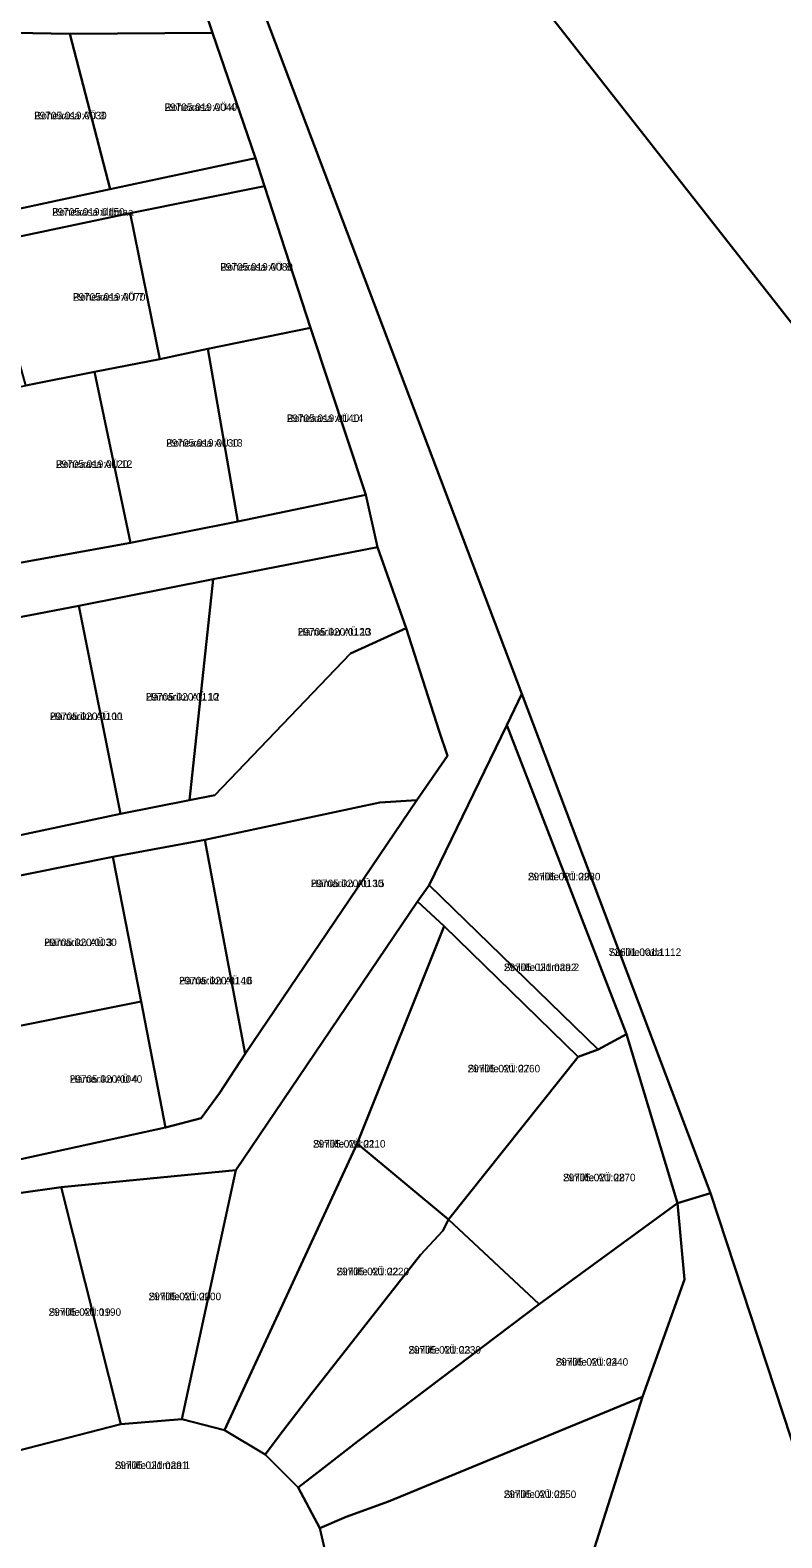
# Model space of a CAD drawing. Extents: x 504287 to 537970, y 6539941 to 6586214.
# Drawn here: x 519555.2 to 519705.5, y 6562734.5 to 6563035.9 of the extents above; entities that cross this region are included whole.
import ezdxf

# ---------------------------------------------------------------- set-up
doc = ezdxf.new("R2010")
doc.units = 0
for name, color, linetype in [('L_AADRESS', 7, 'Continuous'), ('PIIR', 7, 'Continuous'), ('TUNNUS', 7, 'Continuous')]:
    doc.layers.add(name, color=color, linetype=linetype)

msp = doc.modelspace()

# ---------------------------------------------------------------- linework, layer by layer
at = {"layer": 'PIIR'}
for points in [[(519599.74, 6563045.34), (519621.02, 6563054.62), (519628.3, 6563057.8), (519628.55, 6563077.91), (519761.64, 6562908.34), (519935.24, 6562630.59), (519776.33, 6562544.79), (519691.31, 6562803.36), (519653.53, 6562903.18)], [(519379.09, 6562978.83), (519372.84, 6562987.83), (519384.54, 6562993.66), (519400.83, 6563002.24), (519416.85, 6563010.23), (519433.17, 6563018.85), (519452.23, 6563026.37), (519470.82, 6563031.67), (519483.82, 6563036.19), (519500.29, 6563041.06), (519518.28, 6563044.73), (519537.55, 6563044.73), (519555.2, 6563044.87), (519572.77, 6563044.98), (519588.48, 6563045.08), (519591.71, 6563035.32), (519563.15, 6563035.15), (519540.86, 6563035.52), (519516.8, 6563034.6), (519500.02, 6563030.32), (519441.15, 6563010.5), (519419.88, 6562999.55), (519403.66, 6562991.39), (519386.67, 6562982.83)], [(519540.86, 6563035.52), (519563.15, 6563035.15), (519571.21, 6563004.1), (519548.61, 6562999.2)], [(519563.15, 6563035.15), (519591.71, 6563035.32), (519600.31, 6563010.25), (519571.21, 6563004.1)], [(519525.83, 6562994.92), (519548.61, 6562999.2), (519571.21, 6563004.1), (519600.31, 6563010.25), (519602.07, 6563004.65), (519575.22, 6562999.24), (519546.44, 6562993.2), (519517.6, 6562987.28), (519516.29, 6562992.78)], [(519581.16, 6562970.07), (519575.22, 6562999.24), (519602.07, 6563004.65), (519611.33, 6562976.36), (519590.76, 6562972.18)], [(519546.44, 6562993.2), (519575.22, 6562999.24), (519581.16, 6562970.07), (519568.11, 6562967.58), (519554.35, 6562964.83)], [(519590.76, 6562972.18), (519611.33, 6562976.36), (519622.37, 6562942.94), (519596.79, 6562937.66)], [(519568.11, 6562967.58), (519581.16, 6562970.07), (519590.76, 6562972.18), (519596.79, 6562937.66), (519575.3, 6562933.4)], [(519545.51, 6562962.97), (519554.35, 6562964.83), (519568.11, 6562967.58), (519575.3, 6562933.4), (519552.04, 6562929.15)], [(519439.86, 6562830.5), (519435.67, 6562843.73), (519440.22, 6562851.26), (519449.22, 6562868.82), (519462.78, 6562893.96), (519471.15, 6562909.87), (519472.21, 6562912.67), (519506.95, 6562920.11), (519529.47, 6562925.02), (519552.04, 6562929.15), (519575.3, 6562933.4), (519596.79, 6562937.66), (519622.37, 6562942.94), (519624.67, 6562932.47), (519591.81, 6562926.12), (519564.98, 6562920.78), (519545.12, 6562917), (519524.25, 6562912.98), (519501.82, 6562908.68), (519486.02, 6562905.4), (519478.28, 6562899.31), (519449.85, 6562848.78)], [(519587.09, 6562881.9), (519591.81, 6562926.12), (519624.67, 6562932.47), (519630.4, 6562916.3), (519619.27, 6562911.27), (519592.2, 6562882.91)], [(519564.98, 6562920.78), (519591.81, 6562926.12), (519587.09, 6562881.9), (519573.3, 6562879.22)], [(519545.12, 6562917), (519564.98, 6562920.78), (519573.3, 6562879.22), (519552.33, 6562874.74)], [(519653.53, 6562903.18), (519691.31, 6562803.36), (519684.69, 6562801.38), (519674.47, 6562835.18), (519650.53, 6562896.94)], [(519650.53, 6562896.94), (519674.47, 6562835.18), (519668.85, 6562832.11), (519635.06, 6562864.91)], [(519590.14, 6562873.97), (519625.17, 6562881.47), (519632.59, 6562881.91), (519598.25, 6562831.23)], [(519577.45, 6562841.67), (519571.8, 6562870.57), (519590.14, 6562873.97), (519598.25, 6562831.23), (519593.13, 6562823.37), (519589.45, 6562818.38), (519582.34, 6562816.48)], [(519539, 6562863.98), (519571.8, 6562870.57), (519577.45, 6562841.67), (519543.75, 6562834.94)], [(519632.68, 6562861.68), (519635.06, 6562864.91), (519668.85, 6562832.11), (519664.79, 6562830.6), (519638.02, 6562856.73)], [(519585.57, 6562758.19), (519596.38, 6562807.99), (519632.68, 6562861.68), (519638.02, 6562856.73), (519620.66, 6562813.31), (519594.1, 6562755.96)], [(519620.66, 6562813.31), (519638.02, 6562856.73), (519664.79, 6562830.6), (519638.89, 6562798.08)], [(519543.75, 6562834.94), (519577.45, 6562841.67), (519582.34, 6562816.48), (519549.08, 6562809.21)], [(519638.89, 6562798.08), (519664.79, 6562830.6), (519668.85, 6562832.11), (519674.47, 6562835.18), (519684.69, 6562801.38), (519657.02, 6562781.19)], [(519605.92, 6562756.01), (519602.25, 6562751.12), (519594.1, 6562755.96), (519620.66, 6562813.31), (519638.89, 6562798.08), (519637.75, 6562795.86), (519633.28, 6562791.02), (519611.46, 6562763.17)], [(519561.47, 6562804.58), (519596.38, 6562807.99), (519585.57, 6562758.19), (519573.38, 6562757.21)], [(519686.09, 6562786.1), (519684.69, 6562801.38), (519691.31, 6562803.36), (519776.33, 6562544.79), (519790.81, 6562491.04), (519668.48, 6562585.11), (519612.99, 6562537.74), (519597.81, 6562511.81), (519571.82, 6562501.21), (519470.28, 6562430.96), (519586.21, 6562624.97), (519618.95, 6562605.45), (519632.67, 6562641.68), (519641.86, 6562666.36), (519653.05, 6562696.4), (519664.85, 6562722.22), (519677.65, 6562762.65)], [(519544.48, 6562802.17), (519561.47, 6562804.58), (519573.38, 6562757.21), (519548.25, 6562750.73)], [(519618.45, 6562738.66), (519613.18, 6562736.37), (519608.84, 6562744.5), (519613.52, 6562748.13), (519620.72, 6562753.71), (519657.02, 6562781.19), (519684.69, 6562801.38), (519686.09, 6562786.1), (519677.65, 6562762.65), (519626.88, 6562741.71)], [(519613.52, 6562748.13), (519608.84, 6562744.5), (519602.25, 6562751.12), (519605.92, 6562756.01), (519611.46, 6562763.17), (519633.28, 6562791.02), (519637.75, 6562795.86), (519638.89, 6562798.08), (519657.02, 6562781.19), (519620.72, 6562753.71)], [(519664.85, 6562722.22), (519616.08, 6562723.7), (519613.18, 6562736.37), (519618.45, 6562738.66), (519626.88, 6562741.71), (519677.65, 6562762.65)]]:
    msp.add_lwpolyline(points, close=True, dxfattribs=at)
for points in [[(519942.11, 6562942.65), (519866.44, 6562932.46), (519761.64, 6562908.34), (519628.55, 6563077.91)], [(519599.74, 6563045.34), (519653.53, 6562903.18), (519650.53, 6562896.94), (519635.06, 6562864.91), (519632.68, 6562861.68), (519596.38, 6562807.99), (519561.47, 6562804.58), (519544.48, 6562802.17)], [(519549.08, 6562809.21), (519582.34, 6562816.48), (519589.45, 6562818.38), (519593.13, 6562823.37), (519598.25, 6562831.23), (519632.59, 6562881.91), (519638.67, 6562890.8), (519637.03, 6562895.69), (519630.4, 6562916.3), (519624.67, 6562932.47), (519622.37, 6562942.94), (519611.33, 6562976.36), (519602.07, 6563004.65), (519600.31, 6563010.25), (519591.71, 6563035.32), (519588.48, 6563045.08)], [(519552.33, 6562874.74), (519573.3, 6562879.22), (519587.09, 6562881.9), (519592.2, 6562882.91), (519619.27, 6562911.27), (519630.4, 6562916.3), (519637.03, 6562895.69), (519638.67, 6562890.8), (519632.59, 6562881.91), (519625.17, 6562881.47), (519590.14, 6562873.97), (519571.8, 6562870.57), (519539, 6562863.98)], [(519499.7, 6562732.76), (519490.66, 6562742.52), (519481.72, 6562756.29), (519475.03, 6562768.08), (519470.95, 6562782.64), (519465.32, 6562806.79), (519473.24, 6562805.59), (519496.01, 6562767.99), (519520.13, 6562753.47), (519537.45, 6562747.73), (519548.25, 6562750.73), (519573.38, 6562757.21), (519585.57, 6562758.19), (519594.1, 6562755.96), (519602.25, 6562751.12), (519608.84, 6562744.5), (519613.18, 6562736.37), (519616.08, 6562723.7)]]:
    msp.add_lwpolyline(points, dxfattribs=at)

# ---------------------------------------------------------------- texts
at = {"layer": 'L_AADRESS'}
for s, p in [('Roheaasa AÜ 3', (519556.04, 6563018.04)), ('Roheaasa AÜ 4', (519582.11, 6563019.71)), ('Roheaasa üldmaa', (519559.63, 6562998.77)), ('Roheaasa AÜ 8', (519593.27, 6562987.78)), ('Roheaasa AÜ 7', (519563.8, 6562981.78)), ('Roheaasa AÜ 14', (519606.56, 6562957.53)), ('Roheaasa AÜ 13', (519582.45, 6562952.59)), ('Roheaasa AÜ 12', (519560.4, 6562948.36)), ('Hämariku AÜ 13', (519608.75, 6562914.82)), ('Hämariku AÜ 12', (519578.39, 6562901.83)), ('Hämariku AÜ 11', (519559.21, 6562897.95)), ('Hämariku AÜ 15', (519611.37, 6562864.55)), ('Sinilille AÜ 29', (519654.77, 6562865.9)), ('Hämariku AÜ 3', (519558.06, 6562852.76)), ('Sinilille rada', (519670.92, 6562850.79)), ('Sinilille üldmaa 2', (519649.97, 6562847.76)), ('Hämariku AÜ 16', (519585.02, 6562845.11)), ('Hämariku AÜ 4', (519563.16, 6562825.44)), ('Sinilille AÜ 27', (519642.72, 6562827.52)), ('Sinilille AÜ 21', (519611.8, 6562812.48)), ('Sinilille AÜ 28', (519661.79, 6562805.75)), ('Sinilille AÜ 22', (519616.5, 6562786.96)), ('Sinilille AÜ 20', (519578.93, 6562781.97)), ('Sinilille AÜ 19', (519558.93, 6562778.85)), ('Sinilille AÜ 23', (519630.88, 6562771.29)), ('Sinilille AÜ 24', (519660.32, 6562768.88)), ('Sinilille üldmaa 1', (519572.18, 6562748.23)), ('Sinilille AÜ 25', (519649.94, 6562742.43))]:
    msp.add_text(s, height=1.5, dxfattribs=at).set_placement(p)
at = {"layer": 'TUNNUS'}
for s, p in [('29705:019:0030', (519556.04, 6563018.04)), ('29705:019:0040', (519582.11, 6563019.71)), ('29705:019:0150', (519559.63, 6562998.77)), ('29705:019:0080', (519593.27, 6562987.78)), ('29705:019:0070', (519563.8, 6562981.78)), ('29705:019:0140', (519606.56, 6562957.53)), ('29705:019:0130', (519582.45, 6562952.59)), ('29705:019:0120', (519560.4, 6562948.36)), ('29705:020:0120', (519608.75, 6562914.82)), ('29705:020:0110', (519578.39, 6562901.83)), ('29705:020:0100', (519559.21, 6562897.95)), ('29705:020:0130', (519611.37, 6562864.55)), ('29705:021:0280', (519654.77, 6562865.9)), ('29705:020:0030', (519558.06, 6562852.76)), ('72601:001:1112', (519670.92, 6562850.79)), ('29705:021:0292', (519649.97, 6562847.76)), ('29705:020:0140', (519585.02, 6562845.11)), ('29705:020:0040', (519563.16, 6562825.44)), ('29705:021:0260', (519642.72, 6562827.52)), ('29705:021:0210', (519611.8, 6562812.48)), ('29705:021:0270', (519661.79, 6562805.75)), ('29705:021:0220', (519616.5, 6562786.96)), ('29705:021:0200', (519578.93, 6562781.97)), ('29705:021:0190', (519558.93, 6562778.85)), ('29705:021:0230', (519630.88, 6562771.29)), ('29705:021:0240', (519660.32, 6562768.88)), ('29705:021:0291', (519572.18, 6562748.23)), ('29705:021:0250', (519649.94, 6562742.43))]:
    msp.add_text(s, height=1.5, dxfattribs=at).set_placement(p)

doc.saveas('drawing.dxf')
